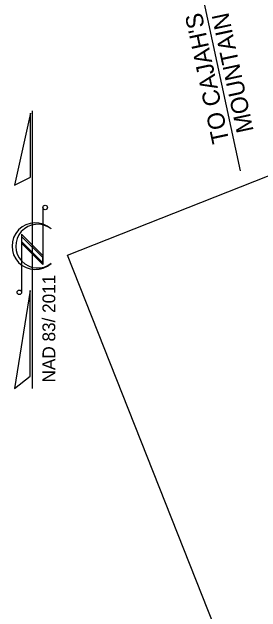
# Model space of a CAD drawing. Extents: x 1247235 to 1260080, y 742320 to 754020.
# Drawn here: x 1249387 to 1250042, y 749050 to 750629 of the extents above; entities that cross this region are included whole.
import ezdxf

# ---------------------------------------------------------------- set-up
doc = ezdxf.new("R2010")
doc.units = 0
for name, color, linetype in [('Old_Level_60', 7, 'Continuous'), ('Prop DSN Text', 7, 'Continuous'), ('Scratch_Level_3', 7, 'Continuous'), ('Sheet North Arrow CELL', 7, 'Continuous')]:
    doc.layers.add(name, color=color, linetype=linetype)

msp = doc.modelspace()

# ---------------------------------------------------------------- linework, layer by layer
at = {"layer": 'Old_Level_60'}
msp.add_line((1249857.1, 750818.6), (1249987.3, 750210.8), dxfattribs=at)
at = {"layer": 'Scratch_Level_3'}
msp.add_lwpolyline([(1251095.3, 746040.1), (1249533.8, 749989.2), (1251115.9, 750614.8), (1252677.6, 746665.7)], close=True, dxfattribs=at)
at = {"layer": 'Sheet North Arrow CELL'}
for p, q in [((1249441.1, 749638.1), (1249441.1, 750369.4)), ((1249468.6, 750114.9), (1249468.6, 749964.8)), ((1249489.3, 750059), (1249490.1, 750058.4)), ((1249468.6, 749988.2), (1249412.7, 750044.2)), ((1249412.7, 750044.2), (1249412.7, 749891.6)), ((1249468.6, 749982.7), (1249412.7, 750038.6)), ((1249412.7, 750038.6), (1249412.7, 750024.9)), ((1249468.6, 749969), (1249412.7, 750024.9)), ((1249412.7, 750024.9), (1249468.6, 749969)), ((1249468.6, 749964.8), (1249412.7, 750020.8)), ((1249468.6, 749969), (1249468.6, 749982.7))]:
    msp.add_line(p, q, dxfattribs=at)
for points in [[(1249436, 750363), (1249394.3, 750173.1), (1249436, 750194.2)], [(1249435.1, 749895.8), (1249393.7, 749638.1), (1249435.1, 749670.8)]]:
    msp.add_lwpolyline(points, close=True, dxfattribs=at)
for centre in [(1249474.6, 750114.8), (1249406.8, 749891.4)]:
    msp.add_circle(centre, 5.96, dxfattribs=at)
for centre, radius, start, end in [((1249448.8, 750012.9), 61.4, 47.84, 312.3941), ((1249454.8, 750012.9), 57.6, 53.095, 308.6287)]:
    msp.add_arc(centre, radius, start, end, dxfattribs=at)

# ---------------------------------------------------------------- texts
at = {"layer": 'Prop DSN Text'}
for s, p in [("TO CAJAH'S", (1249959.2, 750288.2)), ('MOUNTAIN', (1250023.3, 750316.6))]:
    msp.add_text(s, height=45, rotation=102.0916, dxfattribs=at).set_placement(p)
at = {"layer": 'Sheet North Arrow CELL'}
msp.add_text('NAD 83/ 2011', height=33.75, rotation=90, dxfattribs=at).set_placement((1249501.3, 749654.1))

doc.saveas('drawing.dxf')
